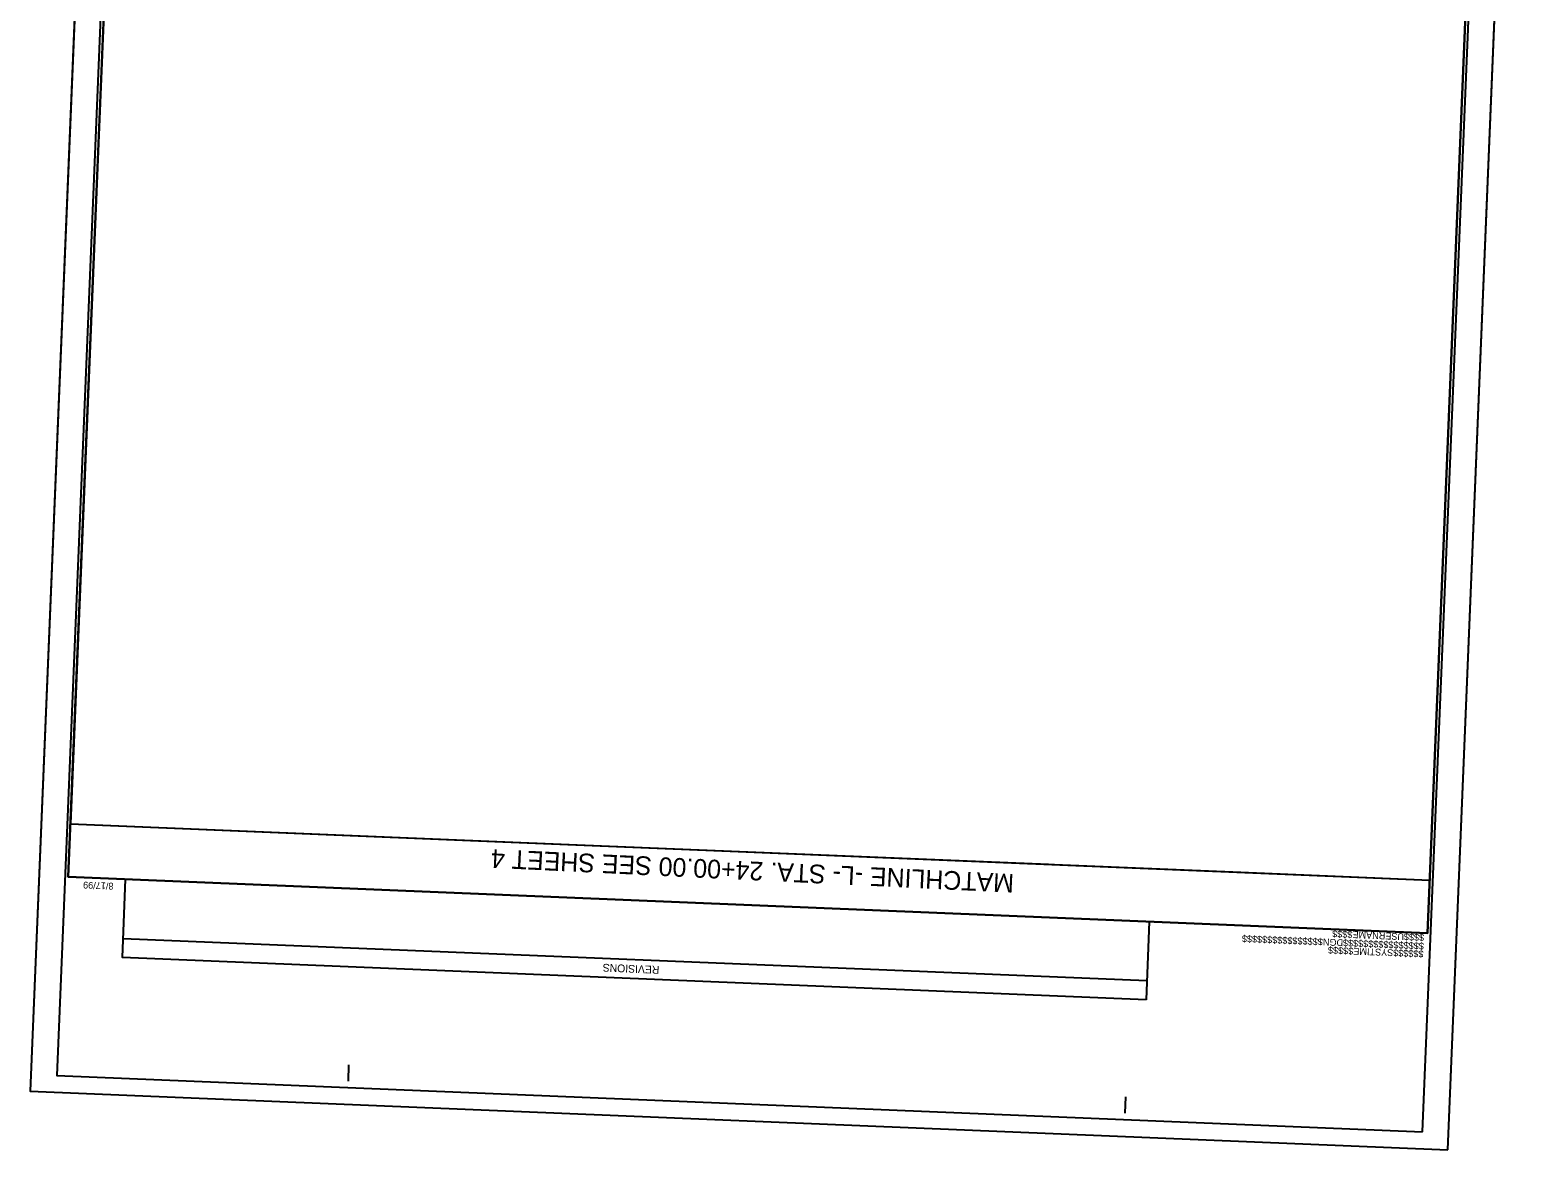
# Model space of a CAD drawing. Extents: x 2265722 to 2266885, y 510440 to 512168.
# Drawn here: x 2265722 to 2266885, y 510440 to 511304 of the extents above; entities that cross this region are included whole.
import ezdxf

# ---------------------------------------------------------------- set-up
doc = ezdxf.new("R2010")
doc.units = 0
for name, color, linetype in [('Matchline', 7, 'Continuous'), ('Matchline Text', 7, 'Continuous'), ('Sheet Block Revision CELL', 7, 'Continuous'), ('Sheet Clip Boundary CELL', 7, 'Continuous'), ('Sheet Cutting Line CELL', 7, 'Continuous'), ('Sheet Layout Plan Border', 7, 'Continuous'), ('Sheet Plan CELL', 7, 'Continuous'), ('Sheet Plan Layout CELL', 7, 'Continuous'), ('Sheet Plot Border Inside CELL', 7, 'Continuous'), ('Sheet Plot Border Outside CELL', 7, 'Continuous')]:
    doc.layers.add(name, color=color, linetype=linetype)

msp = doc.modelspace()

# ---------------------------------------------------------------- linework, layer by layer
at = {"layer": 'Matchline'}
msp.add_line((2266031.1, 510680.2), (2266507.7, 510660.5), dxfattribs=at)
at = {"layer": 'Sheet Block Revision CELL'}
msp.add_line((2266583.5, 510570.5), (2265793.6, 510603.1), dxfattribs=at)
msp.add_lwpolyline([(2266583, 510556), (2265793, 510588.6), (2265795.5, 510649.1), (2266585.4, 510616.4)], close=True, dxfattribs=at)
at = {"layer": 'Sheet Clip Boundary CELL'}
msp.add_lwpolyline([(2265950.3, 510683.5), (2266061.7, 510678.9), (2266649.9, 510654.6), (2266801.9, 510648.3), (2266862.2, 512106.3), (2266024.4, 512140.9), (2266014.5, 511901.8), (2265803.2, 511910.6), (2265752.9, 510691.7)], close=True, dxfattribs=at)
at = {"layer": 'Sheet Cutting Line CELL'}
for p, q in [((2265791.3, 512167.5), (2265721.8, 510485.5)), ((2266815.9, 510440.3), (2266885.4, 512122.3)), ((2265721.8, 510485.5), (2266815.9, 510440.3))]:
    msp.add_line(p, q, dxfattribs=at)
at = {"layer": 'Sheet Layout Plan Border'}
msp.add_lwpolyline([(2266801.9, 510648.3), (2266862.2, 512106.3), (2266024.4, 512140.9), (2266014.5, 511901.8), (2265803.2, 511910.6), (2265752.9, 510691.7)], close=True, dxfattribs=at)
at = {"layer": 'Sheet Plan CELL'}
for p, q in [((2265751.1, 510650.9), (2265751.1, 510650.9)), ((2266800.3, 510607.5), (2266800.3, 510607.5)), ((2265967.4, 510493.3), (2265967.8, 510505.8)), ((2266566.8, 510468.6), (2266567.4, 510481.1))]:
    msp.add_line(p, q, dxfattribs=at)
for points in [[(2265813.1, 512149.7), (2265751.1, 510650.9), (2266800.3, 510607.5), (2266862.2, 512106.3)], [(2266800.3, 510607.5), (2265751.2, 510650.9), (2265804.8, 511949.7), (2265954.7, 511943.6), (2265963, 512143.4), (2266862.2, 512106.3)]]:
    msp.add_lwpolyline(points, close=True, dxfattribs=at)
at = {"layer": 'Sheet Plan Layout CELL'}
msp.add_lwpolyline([(2265751.2, 510650.9), (2266800.3, 510607.5), (2266862.2, 512106.3), (2266024.4, 512140.9), (2266014.5, 511901.8), (2265803.2, 511910.6)], close=True, dxfattribs=at)
at = {"layer": 'Sheet Plot Border Inside CELL'}
msp.add_lwpolyline([(2266796.4, 510454.1), (2266865.2, 512118.7), (2265811.1, 512162.2), (2265742.3, 510497.6)], close=True, dxfattribs=at)
at = {"layer": 'Sheet Plot Border Outside CELL'}
msp.add_lwpolyline([(2266815.9, 510440.3), (2266885.4, 512122.3), (2265791.3, 512167.5), (2265721.8, 510485.5)], close=True, dxfattribs=at)

# ---------------------------------------------------------------- texts
at = {"layer": 'Matchline Text'}
msp.add_text('MATCHLINE -L- STA. 24+00.00 SEE SHEET 4', height=14.4, rotation=177.2667, dxfattribs=at).set_placement((2266481.4, 510653))
at = {"layer": 'Sheet Block Revision CELL'}
msp.add_text('REVISIONS', height=6, rotation=177.6342, dxfattribs=at).set_placement((2266207.5, 510582))
at = {"layer": 'Sheet Plan CELL'}
for s, p in [('8/17/99', (2265786.2, 510646.2)), ('$$$$$$$$$$$$$$$$DGN$$$$$$$$$$$$$$$$', (2266797.6, 510600)), ('$$$$USERNAME$$$$', (2266797.8, 510606.6)), ('$$$$$$SYSTIME$$$$$', (2266797.3, 510593.9))]:
    msp.add_text(s, height=5.25, rotation=177.6342, dxfattribs=at).set_placement(p)

doc.saveas('drawing.dxf')
